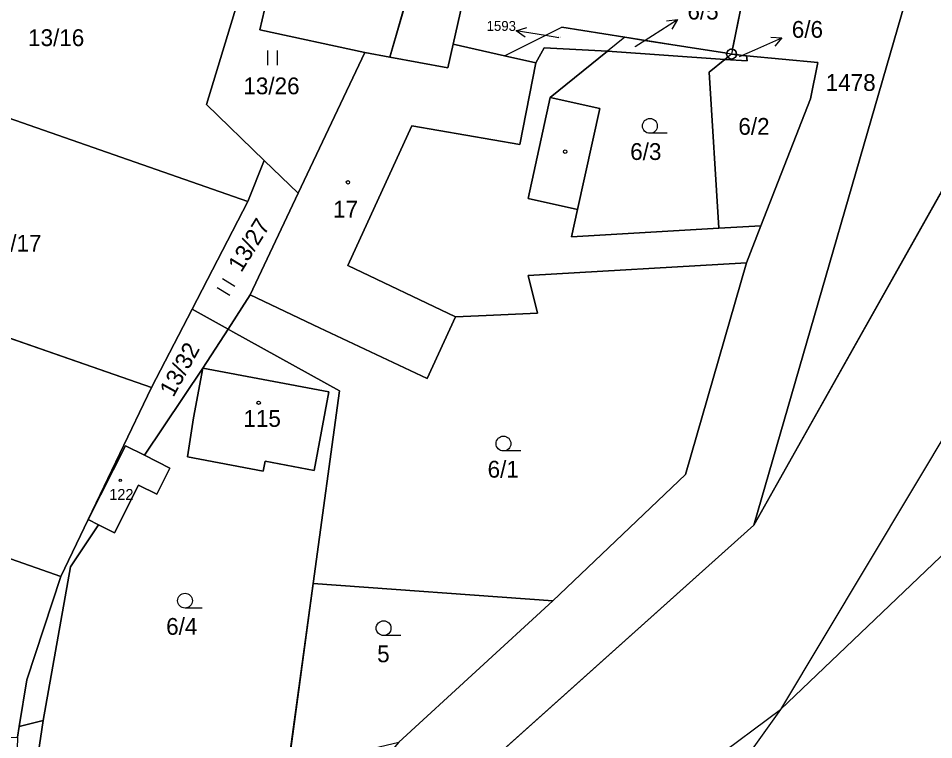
# Model space of a CAD drawing. Extents: x -760642 to -757221, y -1092371 to -1088855.
# Drawn here: x -758998.7 to -758906, y -1089975.4 to -1089902.3 of the extents above; entities that cross this region are included whole.
import ezdxf

# ---------------------------------------------------------------- set-up
doc = ezdxf.new("R2010")
doc.units = 0
for name, color, linetype in [('Vrstva 1', 7, 'Continuous'), ('Vrstva 16', 7, 'Continuous'), ('Vrstva 18', 7, 'Continuous'), ('Vrstva 19', 7, 'Continuous'), ('Vrstva 24', 7, 'Continuous'), ('Vrstva 25', 7, 'Continuous'), ('Vrstva 26', 7, 'Continuous'), ('Vrstva 27', 7, 'Continuous'), ('Vrstva 4', 7, 'Continuous')]:
    doc.layers.add(name, color=color, linetype=linetype)

msp = doc.modelspace()

# ---------------------------------------------------------------- linework, layer by layer
at = {"layer": 'Vrstva 1'}
for p, q in [((-758906.98, -1089894.03), (-758924.22, -1089953.65)), ((-758959.04, -1089899.19), (-758961.07, -1089906.28)), ((-758979.65, -1089911.07), (-758976.58, -1089900.97)), ((-758973.75, -1089901.48), (-758974.24, -1089903.51)), ((-758925.39, -1089900.66), (-758926.48, -1089905.96)), ((-758949.47, -1089906.14), (-758943.66, -1089903.24)), ((-758937.28, -1089904.25), (-758943.66, -1089903.24)), ((-758974.24, -1089903.51), (-758963.62, -1089905.81)), ((-758937.28, -1089904.25), (-758939.03, -1089905.67)), ((-758926.48, -1089905.96), (-758937.28, -1089904.25)), ((-758954.68, -1089904.97), (-758955.22, -1089907.36)), ((-758954.68, -1089904.97), (-758949.47, -1089906.14)), ((-758896.51, -1089904.37), (-758924.22, -1089953.65)), ((-758963.62, -1089905.81), (-758970.35, -1089920.05)), ((-758963.62, -1089905.81), (-758961.07, -1089906.28)), ((-758949.47, -1089906.14), (-758946.3, -1089906.86)), ((-758946.3, -1089906.86), (-758945.45, -1089905.32)), ((-758945.45, -1089905.32), (-758939.03, -1089905.67)), ((-758939.03, -1089905.67), (-758944.83, -1089910.36)), ((-758939.03, -1089905.67), (-758927.15, -1089906.5)), ((-758926.48, -1089905.96), (-758927.15, -1089906.5)), ((-758926.48, -1089905.96), (-758924.97, -1089906.14)), ((-758924.91, -1089906.66), (-758924.97, -1089906.14)), ((-758924.97, -1089906.14), (-758917.76, -1089906.81)), ((-758961.07, -1089906.28), (-758955.22, -1089907.36)), ((-758927.15, -1089906.5), (-758928.74, -1089907.8)), ((-758927.15, -1089906.5), (-758924.91, -1089906.66)), ((-758917.76, -1089906.81), (-758918.5, -1089910.48)), ((-758975.44, -1089920.9), (-759013.29, -1089907.7)), ((-758928.74, -1089907.8), (-758927.77, -1089923.6)), ((-758944.83, -1089910.36), (-758939.82, -1089911.46)), ((-758918.5, -1089910.48), (-758923.51, -1089923.36)), ((-758973.79, -1089916.73), (-758979.65, -1089911.07)), ((-758939.82, -1089911.46), (-758942.06, -1089921.68)), ((-758975.44, -1089920.9), (-758973.79, -1089916.73)), ((-758973.79, -1089916.73), (-758970.35, -1089920.05)), ((-758970.35, -1089920.05), (-758975.21, -1089930.34)), ((-758981.09, -1089931.79), (-758975.44, -1089920.9)), ((-758942.06, -1089921.68), (-758942.67, -1089924.45)), ((-758942.67, -1089924.45), (-758927.77, -1089923.6)), ((-758927.77, -1089923.6), (-758923.51, -1089923.36)), ((-758923.51, -1089923.36), (-758924.97, -1089927.1)), ((-758893.71, -1089925.82), (-758921.51, -1089972.3)), ((-758947.07, -1089928.37), (-758924.97, -1089927.1)), ((-758924.97, -1089927.1), (-758931.13, -1089948.53)), ((-758985.21, -1089939.73), (-759020.24, -1089927.52)), ((-758947.07, -1089928.37), (-758946.14, -1089932.2)), ((-758975.21, -1089930.34), (-758977.45, -1089933.81)), ((-758968.19, -1089933.66), (-758975.21, -1089930.34)), ((-758985.21, -1089939.73), (-758981.09, -1089931.79)), ((-758981.09, -1089931.79), (-758977.45, -1089933.81)), ((-758954.43, -1089932.55), (-758957.31, -1089938.8)), ((-758951.32, -1089932.42), (-758954.43, -1089932.55)), ((-758946.14, -1089932.2), (-758951.32, -1089932.42)), ((-758977.45, -1089933.81), (-758980, -1089937.77)), ((-758977.45, -1089933.81), (-758976.97, -1089934.07)), ((-758957.31, -1089938.8), (-758968.19, -1089933.66)), ((-758976.97, -1089934.07), (-758966.17, -1089940.05)), ((-758980, -1089937.77), (-758985.91, -1089946.58)), ((-758980.94, -1089942.78), (-758980, -1089937.77)), ((-758980, -1089937.77), (-758967.25, -1089940.15)), ((-758994.39, -1089958.84), (-758985.21, -1089939.73)), ((-758966.17, -1089940.05), (-758968.83, -1089959.56)), ((-758967.25, -1089940.15), (-758968.73, -1089948.11)), ((-758981.56, -1089946.72), (-758980.94, -1089942.78)), ((-758987.84, -1089945.61), (-758991.62, -1089953.08)), ((-758985.91, -1089946.58), (-758987.84, -1089945.61)), ((-758983.34, -1089947.87), (-758985.91, -1089946.58)), ((-758981.56, -1089946.72), (-758973.89, -1089948.19)), ((-759027.19, -1089947.34), (-758994.39, -1089958.84)), ((-758984.68, -1089950.51), (-758983.34, -1089947.87)), ((-758973.89, -1089948.19), (-758973.69, -1089947.17)), ((-758973.69, -1089947.17), (-758968.73, -1089948.11)), ((-758895.93, -1089947.85), (-758921.51, -1089972.3)), ((-758931.13, -1089948.53), (-758944.58, -1089961.32)), ((-758988.94, -1089954.44), (-758986.51, -1089949.59)), ((-758986.51, -1089949.59), (-758984.68, -1089950.51)), ((-758991.62, -1089953.08), (-758990.57, -1089953.61)), ((-758990.57, -1089953.61), (-758993.39, -1089957.86)), ((-758990.57, -1089953.61), (-758988.94, -1089954.44)), ((-758924.22, -1089953.65), (-758954.54, -1089980.81)), ((-758993.39, -1089957.86), (-758996.19, -1089973.42)), ((-758997.83, -1089969.3), (-758994.39, -1089958.84)), ((-758968.83, -1089959.56), (-758971.39, -1089978.3)), ((-758968.83, -1089959.56), (-758944.58, -1089961.32)), ((-758944.58, -1089961.32), (-758960.15, -1089975.62)), ((-758998.6, -1089974.04), (-758997.83, -1089969.3)), ((-758921.51, -1089972.3), (-758945.89, -1090006.18)), ((-758933.01, -1089980.82), (-758921.51, -1089972.3)), ((-758998.6, -1089974.04), (-758996.19, -1089973.42)), ((-758996.19, -1089973.42), (-758997.68, -1089983.64)), ((-758998.78, -1089975.12), (-758998.6, -1089974.04))]:
    msp.add_line(p, q, dxfattribs=at)
at = {"layer": 'Vrstva 16'}
for p, q in [((-758934.48, -1089904.08), (-758931.953, -1089902.463)), ((-758945.32, -1089904.08), (-758948.282, -1089903.607)), ((-758943.96, -1089904.3), (-758945.32, -1089904.08)), ((-758936.23, -1089905.2), (-758934.48, -1089904.08)), ((-758924.12, -1089905.53), (-758921.378, -1089904.313)), ((-758925.66, -1089906.21), (-758924.12, -1089905.53))]:
    msp.add_line(p, q, dxfattribs=at)
for points in [[(-758933.065, -1089902.581), (-758931.953, -1089902.463), (-758932.526, -1089903.423)], [(-758947.374, -1089904.258), (-758948.282, -1089903.607), (-758947.216, -1089903.271)], [(-758922.495, -1089904.262), (-758921.378, -1089904.313), (-758922.089, -1089905.176)]]:
    msp.add_lwpolyline(points, dxfattribs=at)
at = {"layer": 'Vrstva 24'}
for radius in [0.5, 0.0327]:
    msp.add_circle((-758926.48, -1089905.96), radius, dxfattribs=at)
at = {"layer": 'Vrstva 25'}
for p, q in [((-758973.457, -1089905.595), (-758973.457, -1089907.095)), ((-758972.435, -1089907.095), (-758972.435, -1089905.595)), ((-758933, -1089913.98), (-758934.75, -1089913.98)), ((-758976.755, -1089929.497), (-758978.032, -1089928.71)), ((-758978.568, -1089929.58), (-758977.291, -1089930.367)), ((-758947.82, -1089946.14), (-758949.57, -1089946.14)), ((-758980.06, -1089962.05), (-758981.81, -1089962.05)), ((-758959.96, -1089964.83), (-758961.71, -1089964.83))]:
    msp.add_line(p, q, dxfattribs=at)
for centre, radius in [((-758934.75, -1089913.23), 0.75), ((-758943.33, -1089915.84), 0.175), ((-758965.32, -1089918.94), 0.175), ((-758974.36, -1089941.26), 0.175), ((-758949.57, -1089945.39), 0.75), ((-758988.37, -1089949.11), 0.117), ((-758981.81, -1089961.3), 0.75), ((-758961.71, -1089964.08), 0.75)]:
    msp.add_circle(centre, radius, dxfattribs=at)
at = {"layer": 'Vrstva 26'}
for points in [[(-758954.54, -1089980.81), (-758924.22, -1089953.65), (-758906.98, -1089894.03), (-758906.61, -1089872.1), (-758906.87, -1089846.64), (-758914.44, -1089833.07), (-758916.16, -1089832.7), (-758917.76, -1089837.18), (-758918.02, -1089837.91), (-758914.54, -1089839.88), (-758912.54, -1089841.02), (-758911.16, -1089848.91), (-758911.94, -1089866.36), (-758911.97, -1089868.62), (-758912.05, -1089870.1), (-758911.5, -1089870.13), (-758912.27, -1089889.66), (-758912.48, -1089895.12), (-758912.653, -1089895.217)], [(-758890.51, -1089841.85), (-758883.28, -1089843.38), (-758878.54, -1089845.15), (-758876.54, -1089845.89), (-758876.11, -1089844.03), (-758894.95, -1089837.25), (-758914.44, -1089833.07), (-758906.87, -1089846.64), (-758906.61, -1089872.1), (-758906.98, -1089894.03), (-758924.22, -1089953.65), (-758896.51, -1089904.37), (-758882.89, -1089871.97), (-758880.03, -1089860.89), (-758899.22, -1089859.48), (-758899.02, -1089855.5), (-758898.44, -1089841.46), (-758890.51, -1089841.85)], [(-758972.49, -1089896.18), (-758973.75, -1089901.48), (-758974.24, -1089903.51), (-758963.62, -1089905.81), (-758961.07, -1089906.28), (-758959.04, -1089899.19), (-758957.66, -1089894.38), (-758957.24, -1089892), (-758955.77, -1089884.91), (-758961.05, -1089884.33), (-758962.25, -1089883.95), (-758966.39, -1089895.11), (-758971.7, -1089893.76), (-758972.49, -1089896.18)], [(-758975.44, -1089920.9), (-758973.79, -1089916.73), (-758979.65, -1089911.07), (-758976.58, -1089900.97), (-758975.89, -1089898.68), (-759006.34, -1089887.89), (-759013.29, -1089907.7), (-758975.44, -1089920.9)], [(-758925.492, -1089900.17), (-758926.04, -1089897.53), (-758928.42, -1089898.96), (-758947.1, -1089901.26), (-758945.46, -1089894.43), (-758957.24, -1089892), (-758957.66, -1089894.38), (-758952.62, -1089895.82), (-758954.68, -1089904.97), (-758949.47, -1089906.14), (-758945.337, -1089904.077), (-758943.66, -1089903.24), (-758937.28, -1089904.25), (-758935.248, -1089904.572), (-758926.974, -1089905.882)], [(-758954.68, -1089904.97), (-758952.62, -1089895.82), (-758957.66, -1089894.38), (-758959.04, -1089899.19), (-758961.07, -1089906.28), (-758955.22, -1089907.36), (-758954.68, -1089904.97)], [(-758976.58, -1089900.97), (-758979.65, -1089911.07), (-758973.79, -1089916.73), (-758970.35, -1089920.05), (-758963.62, -1089905.81), (-758974.24, -1089903.51), (-758973.75, -1089901.48), (-758976.58, -1089900.97)], [(-758926.379, -1089905.47), (-758925.491, -1089901.15)], [(-758925.491, -1089901.15), (-758926.379, -1089905.47)], [(-758926.974, -1089905.882), (-758935.248, -1089904.572), (-758937.28, -1089904.25), (-758939.03, -1089905.67), (-758927.15, -1089906.5), (-758926.869, -1089906.274)], [(-758965.32, -1089927.38), (-758958.85, -1089913.24), (-758947.92, -1089915.11), (-758946.3, -1089906.86), (-758949.47, -1089906.14), (-758954.68, -1089904.97), (-758955.22, -1089907.36), (-758961.07, -1089906.28), (-758963.62, -1089905.81), (-758970.35, -1089920.05), (-758975.21, -1089930.34), (-758968.19, -1089933.66), (-758957.31, -1089938.8), (-758954.43, -1089932.55), (-758965.32, -1089927.38)], [(-758947.92, -1089915.11), (-758958.85, -1089913.24), (-758965.32, -1089927.38), (-758954.43, -1089932.55), (-758951.32, -1089932.42), (-758946.14, -1089932.2), (-758947.07, -1089928.37), (-758924.97, -1089927.1), (-758923.51, -1089923.36), (-758927.77, -1089923.6), (-758942.67, -1089924.45), (-758942.06, -1089921.68), (-758947.07, -1089920.58), (-758944.83, -1089910.36), (-758939.03, -1089905.67), (-758945.45, -1089905.32), (-758946.3, -1089906.86), (-758947.92, -1089915.11)], [(-758925.984, -1089906.019), (-758925.388, -1089906.09), (-758924.97, -1089906.14), (-758917.76, -1089906.81), (-758918.5, -1089910.48), (-758923.51, -1089923.36), (-758924.97, -1089927.1), (-758931.13, -1089948.53), (-758944.58, -1089961.32), (-758960.15, -1089975.62)], [(-758927.77, -1089923.6), (-758928.74, -1089907.8), (-758927.15, -1089906.5), (-758939.03, -1089905.67), (-758944.83, -1089910.36), (-758939.82, -1089911.46), (-758942.06, -1089921.68), (-758942.67, -1089924.45), (-758927.77, -1089923.6)], [(-758927.77, -1089923.6), (-758923.51, -1089923.36), (-758918.5, -1089910.48), (-758917.76, -1089906.81), (-758924.97, -1089906.14), (-758924.91, -1089906.66), (-758927.15, -1089906.5), (-758928.74, -1089907.8), (-758927.77, -1089923.6)], [(-758926.869, -1089906.274), (-758927.15, -1089906.5), (-758924.91, -1089906.66), (-758924.97, -1089906.14), (-758925.388, -1089906.09), (-758925.984, -1089906.019)], [(-758926.505, -1089905.981), (-758926.869, -1089906.274)], [(-758925.984, -1089906.019), (-758926.448, -1089905.964)], [(-758981.09, -1089931.79), (-758975.44, -1089920.9), (-759013.29, -1089907.7), (-759020.24, -1089927.52), (-758985.21, -1089939.73), (-758981.09, -1089931.79)], [(-758944.83, -1089910.36), (-758947.07, -1089920.58), (-758942.06, -1089921.68), (-758939.82, -1089911.46), (-758944.83, -1089910.36)], [(-758973.79, -1089916.73), (-758975.44, -1089920.9), (-758981.09, -1089931.79), (-758977.45, -1089933.81), (-758975.21, -1089930.34), (-758970.35, -1089920.05), (-758973.79, -1089916.73)], [(-758968.83, -1089959.56), (-758944.58, -1089961.32), (-758931.13, -1089948.53), (-758924.97, -1089927.1), (-758947.07, -1089928.37), (-758946.14, -1089932.2), (-758951.32, -1089932.42), (-758954.43, -1089932.55), (-758957.31, -1089938.8), (-758968.19, -1089933.66), (-758975.21, -1089930.34), (-758977.45, -1089933.81), (-758976.97, -1089934.07), (-758966.17, -1089940.05), (-758968.83, -1089959.56)], [(-758991.622, -1089953.079), (-758985.21, -1089939.73), (-759020.24, -1089927.52), (-759027.19, -1089947.34), (-758994.39, -1089958.84), (-758991.622, -1089953.079)], [(-758980, -1089937.77), (-758977.45, -1089933.81), (-758981.09, -1089931.79), (-758985.21, -1089939.73), (-758991.622, -1089953.079), (-758991.62, -1089953.08), (-758987.84, -1089945.61), (-758985.91, -1089946.58), (-758980, -1089937.77)], [(-758997.68, -1089983.64), (-758994.32, -1089983.61), (-758971.39, -1089978.3), (-758968.83, -1089959.56), (-758966.17, -1089940.05), (-758976.97, -1089934.07), (-758977.45, -1089933.81), (-758980, -1089937.77), (-758967.25, -1089940.15), (-758968.73, -1089948.11), (-758973.69, -1089947.17), (-758973.89, -1089948.19), (-758981.56, -1089946.72), (-758980.94, -1089942.78), (-758980, -1089937.77), (-758985.91, -1089946.58), (-758983.34, -1089947.87), (-758984.68, -1089950.51), (-758986.51, -1089949.59), (-758988.94, -1089954.44), (-758990.57, -1089953.61), (-758993.39, -1089957.86), (-758996.19, -1089973.42), (-758997.68, -1089983.64)], [(-758973.69, -1089947.17), (-758968.73, -1089948.11), (-758967.25, -1089940.15), (-758980, -1089937.77), (-758980.94, -1089942.78), (-758981.56, -1089946.72), (-758973.89, -1089948.19), (-758973.69, -1089947.17)], [(-758990.57, -1089953.61), (-758988.94, -1089954.44), (-758986.51, -1089949.59), (-758984.68, -1089950.51), (-758983.34, -1089947.87), (-758985.91, -1089946.58), (-758987.84, -1089945.61), (-758991.62, -1089953.08), (-758990.57, -1089953.61)], [(-759038.26, -1089978.92), (-759017, -1089976.03), (-758998.78, -1089975.12), (-758998.6, -1089974.04), (-758997.83, -1089969.3), (-758994.39, -1089958.84), (-759027.19, -1089947.34), (-759038.26, -1089978.92)], [(-758991.622, -1089953.079), (-758994.39, -1089958.84), (-758997.83, -1089969.3), (-758998.6, -1089974.04), (-758996.19, -1089973.42), (-758993.39, -1089957.86), (-758990.57, -1089953.61), (-758991.62, -1089953.08), (-758991.622, -1089953.079)], [(-758971.39, -1089978.3), (-758960.15, -1089975.62), (-758944.58, -1089961.32), (-758968.83, -1089959.56), (-758971.39, -1089978.3)], [(-758997.68, -1089983.64), (-758996.19, -1089973.42), (-758998.6, -1089974.04), (-758998.78, -1089975.12), (-758998.83, -1089977.51), (-759020.05, -1089980.9), (-759036.53, -1089981.03), (-759038.26, -1089978.92), (-759045.79, -1089979.32), (-759068.24, -1089977.41), (-759067.14, -1089989.45), (-758997.68, -1089983.64)]]:
    msp.add_lwpolyline(points, dxfattribs=at)
for radius, start, end in [(0.5, 171.00286, 180), (0.5, 180, 218.86778), (0.5, 78.37857, 171.00286), (0.5, 218.86778, 353.20212), (0.5, 218.86778, 353.20212), (0.0327, 218.86778, 353.20212), (0.5, 0, 78.37857), (0.5, 353.20212, 0)]:
    msp.add_arc((-758926.48, -1089905.96), radius, start, end, dxfattribs=at)
at = {"layer": 'Vrstva 27'}
msp.add_lwpolyline([(-758997.68, -1089983.64), (-758994.32, -1089983.61), (-758971.39, -1089978.3), (-758960.15, -1089975.62), (-758963.14, -1089979.05), (-758965.97, -1089983.82), (-758954.54, -1089980.81), (-758924.22, -1089953.65), (-758896.51, -1089904.37), (-758882.89, -1089871.97), (-758880.03, -1089860.89), (-758876.11, -1089844.03), (-758874.2, -1089845.26), (-758873.57, -1089841.83), (-758872.87, -1089838.03), (-758872.24, -1089834.59), (-758895.18, -1089829.55), (-758908.4, -1089826.64), (-758937.97, -1089820.13)], dxfattribs=at)
at = {"layer": 'Vrstva 4'}
for p, q in [((-758952.62, -1089895.82), (-758954.68, -1089904.97)), ((-758947.92, -1089915.11), (-758946.3, -1089906.86)), ((-758947.07, -1089920.58), (-758944.83, -1089910.36)), ((-758965.32, -1089927.38), (-758958.85, -1089913.24)), ((-758958.85, -1089913.24), (-758947.92, -1089915.11)), ((-758947.07, -1089920.58), (-758942.06, -1089921.68)), ((-758965.32, -1089927.38), (-758954.43, -1089932.55))]:
    msp.add_line(p, q, dxfattribs=at)

# ---------------------------------------------------------------- texts
at = {"layer": 'Vrstva 16'}
for s, height, p in [('6/5', 1.7, (-758930.95, -1089902.46)), ('1593', 1, (-758951.28, -1089903.61)), ('6/6', 1.7, (-758920.38, -1089904.31))]:
    msp.add_text(s, height=height, dxfattribs=at).set_placement(p)
at = {"layer": 'Vrstva 18'}
for s, height, p in [('13/16', 1.7, (-758997.7, -1089905.15)), ('1593', 0.1, (-758944.06, -1089904.3)), ('6/5', 0.1, (-758936.316, -1089905.2)), ('6/6', 0.1, (-758925.744, -1089906.21)), ('1478', 1.7, (-758916.948, -1089909.69)), ('13/26', 1.7, (-758975.904, -1089910.03)), ('6/2', 1.7, (-758925.79, -1089914.13)), ('6/3', 1.7, (-758936.74, -1089916.68)), ('13/17', 1.7, (-759002.03, -1089925.96)), ('6/1', 1.7, (-758951.176, -1089948.84)), ('6/4', 1.7, (-758983.722, -1089964.75)), ('5', 1.7, (-758962.359, -1089967.53))]:
    msp.add_text(s, height=height, dxfattribs=at).set_placement(p)
for s, rotation, p in [('13/27', 58.35231, (-758976.114, -1089928.147)), ('13/32', 61.34292, (-758982.99, -1089940.77))]:
    msp.add_text(s, height=1.7, rotation=rotation, dxfattribs=at).set_placement(p)
at = {"layer": 'Vrstva 19'}
for s, height, p in [('17', 1.7, (-758966.82, -1089922.51)), ('115', 1.7, (-758975.902, -1089943.7)), ('122', 1.1, (-758989.484, -1089951.09))]:
    msp.add_text(s, height=height, dxfattribs=at).set_placement(p)

doc.saveas('drawing.dxf')
